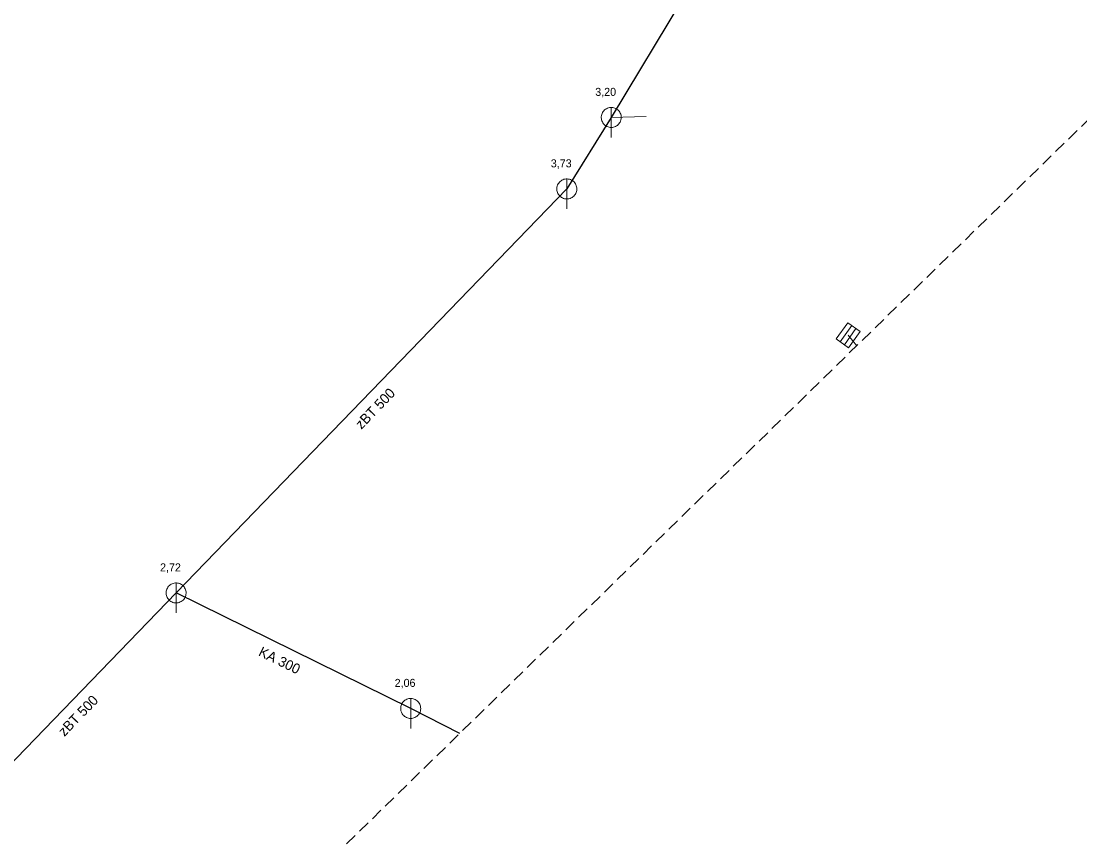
# Model space of a CAD drawing. Extents: x -724334 to -723692, y -972150 to -970648.
# Drawn here: x -723903.3 to -723797.5, y -970873.5 to -970791.8 of the extents above; entities that cross this region are included whole.
import ezdxf

# ---------------------------------------------------------------- set-up
doc = ezdxf.new("R2010")
doc.units = 0
doc.header["$LTSCALE"] = 0.4
doc.linetypes.add('MEDIUM_DASHED', pattern=[4.5, 3, -1.5])
for name, color, linetype, lineweight in [('1', 7, 'Continuous', 25), ('11', 7, 'Continuous', 13), ('14', 7, 'Continuous', 25), ('22', 7, 'Continuous', 13)]:
    doc.layers.add(name, color=color, linetype=linetype, lineweight=lineweight)

msp = doc.modelspace()

# ---------------------------------------------------------------- linework, layer by layer
at = {"layer": '1', "linetype": 'MEDIUM_DASHED'}
msp.add_lwpolyline([(-723848.074, -970648.428), (-723714.095, -970720.999), (-724065.788, -971064.318), (-723792.249, -971201.088), (-723702.93, -971508.122), (-723691.766, -972150.101), (-723842.491, -972097.068), (-723864.821, -971424.385), (-723982.052, -971259.703), (-724333.745, -971117.352)], close=True, dxfattribs=at)
at = {"layer": '11'}
for p, q in [((-723840.862, -970801.322), (-723844.359, -970801.41)), ((-723820.68, -970823.16), (-723819.837, -970824.223))]:
    msp.add_line(p, q, dxfattribs=at)
at = {"layer": '14'}
for p, q in [((-723821.43, -970763.34), (-723844.359, -970801.41)), ((-723844.359, -970801.41), (-723848.8, -970808.55)), ((-723848.8, -970808.55), (-723887.84, -970848.91)), ((-723887.84, -970848.91), (-723908.14, -970869.91)), ((-723864.399, -970860.449), (-723887.84, -970848.91)), ((-723859.495, -970862.936), (-723864.399, -970860.449))]:
    msp.add_line(p, q, dxfattribs=at)
at = {"layer": '22'}
for p, q in [((-723844.359, -970803.41), (-723844.358, -970800.41)), ((-723848.8, -970810.55), (-723848.799, -970807.55)), ((-723821.475, -970823.834), (-723820.314, -970822.205)), ((-723821.068, -970824.124), (-723819.907, -970822.496)), ((-723887.84, -970850.91), (-723887.839, -970847.91)), ((-723864.399, -970862.449), (-723864.398, -970859.449))]:
    msp.add_line(p, q, dxfattribs=at)
for points in [[(-723843.359, -970801.41), (-723843.364, -970801.301), (-723843.382, -970801.193), (-723843.412, -970801.087), (-723843.452, -970800.986), (-723843.504, -970800.889), (-723843.566, -970800.799), (-723843.638, -970800.716), (-723843.718, -970800.642), (-723843.806, -970800.576), (-723843.9, -970800.521), (-723844, -970800.476), (-723844.105, -970800.443), (-723844.212, -970800.421), (-723844.321, -970800.411), (-723844.431, -970800.413), (-723844.539, -970800.427), (-723844.646, -970800.452), (-723844.749, -970800.489), (-723844.847, -970800.538), (-723844.939, -970800.596), (-723845.025, -970800.665), (-723845.102, -970800.742), (-723845.171, -970800.828), (-723845.23, -970800.92), (-723845.278, -970801.018), (-723845.315, -970801.121), (-723845.341, -970801.228), (-723845.355, -970801.336), (-723845.358, -970801.446), (-723845.348, -970801.555), (-723845.327, -970801.662), (-723845.293, -970801.766), (-723845.249, -970801.866), (-723845.194, -970801.961), (-723845.128, -970802.049), (-723845.054, -970802.129), (-723844.971, -970802.201), (-723844.881, -970802.263), (-723844.785, -970802.315), (-723844.683, -970802.356), (-723844.578, -970802.386), (-723844.47, -970802.404), (-723844.36, -970802.41), (-723844.251, -970802.404), (-723844.143, -970802.386), (-723844.038, -970802.357), (-723843.936, -970802.316), (-723843.839, -970802.264), (-723843.749, -970802.202), (-723843.666, -970802.131), (-723843.591, -970802.051), (-723843.526, -970801.963), (-723843.47, -970801.869), (-723843.426, -970801.769), (-723843.392, -970801.665), (-723843.37, -970801.557), (-723843.36, -970801.448)], [(-723847.8, -970808.55), (-723847.805, -970808.441), (-723847.823, -970808.333), (-723847.853, -970808.227), (-723847.893, -970808.126), (-723847.945, -970808.029), (-723848.007, -970807.939), (-723848.079, -970807.856), (-723848.159, -970807.782), (-723848.247, -970807.716), (-723848.341, -970807.661), (-723848.441, -970807.616), (-723848.546, -970807.583), (-723848.653, -970807.561), (-723848.762, -970807.551), (-723848.872, -970807.553), (-723848.98, -970807.567), (-723849.087, -970807.592), (-723849.19, -970807.629), (-723849.288, -970807.678), (-723849.38, -970807.736), (-723849.466, -970807.805), (-723849.543, -970807.882), (-723849.612, -970807.968), (-723849.671, -970808.06), (-723849.719, -970808.158), (-723849.756, -970808.261), (-723849.782, -970808.368), (-723849.796, -970808.476), (-723849.799, -970808.586), (-723849.789, -970808.695), (-723849.768, -970808.802), (-723849.734, -970808.906), (-723849.69, -970809.006), (-723849.635, -970809.101), (-723849.569, -970809.189), (-723849.495, -970809.269), (-723849.412, -970809.341), (-723849.322, -970809.403), (-723849.226, -970809.455), (-723849.124, -970809.496), (-723849.019, -970809.526), (-723848.911, -970809.544), (-723848.801, -970809.55), (-723848.692, -970809.544), (-723848.584, -970809.526), (-723848.479, -970809.497), (-723848.377, -970809.456), (-723848.28, -970809.404), (-723848.19, -970809.342), (-723848.107, -970809.271), (-723848.032, -970809.191), (-723847.967, -970809.103), (-723847.911, -970809.009), (-723847.867, -970808.909), (-723847.833, -970808.805), (-723847.811, -970808.697), (-723847.801, -970808.588)], [(-723821.883, -970823.543), (-723820.721, -970821.915), (-723819.5, -970822.786), (-723820.661, -970824.414)], [(-723886.84, -970848.91), (-723886.845, -970848.801), (-723886.863, -970848.693), (-723886.893, -970848.587), (-723886.933, -970848.486), (-723886.985, -970848.389), (-723887.047, -970848.299), (-723887.119, -970848.216), (-723887.199, -970848.142), (-723887.287, -970848.076), (-723887.381, -970848.021), (-723887.481, -970847.976), (-723887.586, -970847.943), (-723887.693, -970847.921), (-723887.802, -970847.911), (-723887.912, -970847.913), (-723888.02, -970847.927), (-723888.127, -970847.952), (-723888.23, -970847.989), (-723888.328, -970848.038), (-723888.42, -970848.096), (-723888.506, -970848.165), (-723888.583, -970848.242), (-723888.652, -970848.328), (-723888.711, -970848.42), (-723888.759, -970848.518), (-723888.796, -970848.621), (-723888.822, -970848.728), (-723888.836, -970848.836), (-723888.839, -970848.946), (-723888.829, -970849.055), (-723888.808, -970849.162), (-723888.774, -970849.266), (-723888.73, -970849.366), (-723888.675, -970849.461), (-723888.609, -970849.549), (-723888.535, -970849.629), (-723888.452, -970849.701), (-723888.362, -970849.763), (-723888.266, -970849.815), (-723888.164, -970849.856), (-723888.059, -970849.886), (-723887.951, -970849.904), (-723887.841, -970849.91), (-723887.732, -970849.904), (-723887.624, -970849.886), (-723887.519, -970849.857), (-723887.417, -970849.816), (-723887.32, -970849.764), (-723887.23, -970849.702), (-723887.147, -970849.631), (-723887.072, -970849.551), (-723887.007, -970849.463), (-723886.951, -970849.369), (-723886.907, -970849.269), (-723886.873, -970849.165), (-723886.851, -970849.057), (-723886.841, -970848.948)], [(-723863.399, -970860.449), (-723863.404, -970860.34), (-723863.422, -970860.232), (-723863.452, -970860.126), (-723863.492, -970860.025), (-723863.544, -970859.928), (-723863.606, -970859.838), (-723863.678, -970859.755), (-723863.758, -970859.681), (-723863.846, -970859.615), (-723863.94, -970859.56), (-723864.04, -970859.515), (-723864.145, -970859.482), (-723864.252, -970859.46), (-723864.361, -970859.45), (-723864.471, -970859.452), (-723864.579, -970859.466), (-723864.686, -970859.491), (-723864.789, -970859.528), (-723864.887, -970859.577), (-723864.979, -970859.635), (-723865.065, -970859.704), (-723865.142, -970859.781), (-723865.211, -970859.867), (-723865.27, -970859.959), (-723865.318, -970860.057), (-723865.355, -970860.16), (-723865.381, -970860.267), (-723865.395, -970860.375), (-723865.398, -970860.485), (-723865.388, -970860.594), (-723865.367, -970860.701), (-723865.333, -970860.805), (-723865.289, -970860.905), (-723865.234, -970861), (-723865.168, -970861.088), (-723865.094, -970861.168), (-723865.011, -970861.24), (-723864.921, -970861.302), (-723864.825, -970861.354), (-723864.723, -970861.395), (-723864.618, -970861.425), (-723864.51, -970861.443), (-723864.4, -970861.449), (-723864.291, -970861.443), (-723864.183, -970861.425), (-723864.078, -970861.396), (-723863.976, -970861.355), (-723863.879, -970861.303), (-723863.789, -970861.241), (-723863.706, -970861.17), (-723863.631, -970861.09), (-723863.566, -970861.002), (-723863.51, -970860.908), (-723863.466, -970860.808), (-723863.432, -970860.704), (-723863.41, -970860.596), (-723863.4, -970860.487)]]:
    msp.add_lwpolyline(points, close=True, dxfattribs=at)

# ---------------------------------------------------------------- texts
at = {"layer": '1'}
for s, p in [('3,20', (-723845.959, -970799.257)), ('3,73', (-723850.4, -970806.397)), ('2,72', (-723889.44, -970846.757)), ('2,06', (-723866, -970858.297))]:
    msp.add_text(s, height=0.8, dxfattribs=at).set_placement(p)
for s, rotation, p in [('zBT 500 ', 46, (-723869.326, -970832.625)), ('KA 300', 334, (-723879.688, -970855.135)), ('zBT 500 ', 46, (-723898.995, -970863.305))]:
    msp.add_text(s, height=1, rotation=rotation, dxfattribs=at).set_placement(p)

doc.saveas('drawing.dxf')
